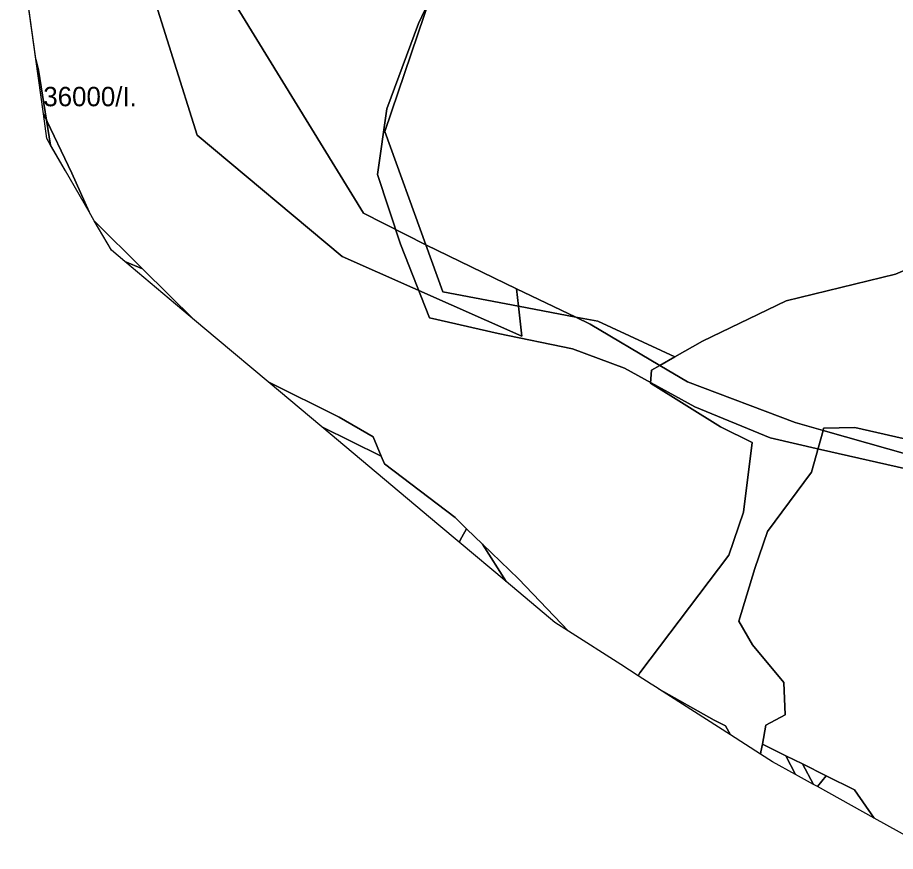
# Model space of a CAD drawing. Extents: x -537068 to -534056, y -1176840 to -1172401.
# Drawn here: x -535737.3 to -535510.5, y -1176827.8 to -1176612.4 of the extents above; entities that cross this region are included whole.
import ezdxf

# ---------------------------------------------------------------- set-up
doc = ezdxf.new("R2010")
doc.units = 0
for name, color, linetype in [('95630013', 7, 'Continuous'), ('95640013', 7, 'Continuous'), ('95660013', 7, 'Continuous')]:
    doc.layers.add(name, color=color, linetype=linetype)

msp = doc.modelspace()

# ---------------------------------------------------------------- linework, layer by layer
at = {"layer": '95630013'}
for points in [[(-535621.12, -1176508.44), (-535627.42, -1176514.05), (-535663.52, -1176546.21), (-535682.87, -1176606.01), (-535647.88, -1176662.99), (-535631.81, -1176671.18), (-535627.41, -1176683.32), (-535607.84, -1176687.01), (-535606.97, -1176694.7), (-535653.38, -1176674.17), (-535690.89, -1176642.78), (-535703.45, -1176602.79), (-535678.44, -1176529.22), (-535628.68, -1176502.86)], [(-535611.19, -1176513.92), (-535537.73, -1176516.12), (-535481.66, -1176536.93), (-535487.75, -1176593.96), (-535547.63, -1176597.67), (-535617.46, -1176602.04), (-535616.99, -1176606.16), (-535547.67, -1176601.79), (-535488.18, -1176598.05), (-535496.14, -1176672.63), (-535510.43, -1176678.69), (-535538.74, -1176685.61), (-535560.3, -1176696.02), (-535567.5, -1176700.1), (-535587.32, -1176690.88), (-535593.03, -1176689.8), (-535608.35, -1176682.47), (-535631.81, -1176671.18), (-535642.41, -1176641.9), (-535625.41, -1176591.75), (-535625.2, -1176543.89)], [(-535729.7, -1176643.72), (-535730.58, -1176637.35), (-535723.23, -1176652.66), (-535718.78, -1176662.62), (-535724.88, -1176652.06)], [(-535709.56, -1176675.47), (-535713.04, -1176672.55), (-535717.46, -1176664.91), (-535704.95, -1176677.3)], [(-535691.56, -1176690.57), (-535709.56, -1176675.47), (-535704.95, -1176677.3)], [(-535607.84, -1176687.01), (-535608.35, -1176682.47), (-535593.03, -1176689.8)], [(-535587.32, -1176690.88), (-535567.5, -1176700.1), (-535571.31, -1176702.26), (-535589.3, -1176691.59), (-535593.03, -1176689.8)], [(-535658.68, -1176718.16), (-535672.54, -1176706.53), (-535654.19, -1176715.67), (-535645.43, -1176720.75), (-535643.3, -1176725.75)], [(-535529.02, -1176718.5), (-535520.93, -1176718.34), (-535504.72, -1176722), (-535501.5, -1176722.89), (-535481.43, -1176726.23), (-535481.42, -1176725.84), (-535431.83, -1176733.13), (-535331.55, -1176707.87), (-535331.62, -1176708.58), (-535368.4, -1176721.4), (-535400.69, -1176729.98), (-535428.42, -1176735.02), (-535446.08, -1176733.53), (-535500.92, -1176727.08), (-535529.17, -1176719.06)], [(-535658.68, -1176718.16), (-535643.3, -1176725.75), (-535642.47, -1176727.68), (-535624.25, -1176741.59), (-535621.28, -1176744.45), (-535622.5, -1176746.61), (-535623.22, -1176747.9), (-535628.42, -1176743.54)], [(-535622.5, -1176746.61), (-535621.28, -1176744.45), (-535617.15, -1176748.46), (-535611.07, -1176758.1), (-535623.22, -1176747.9)], [(-535611.07, -1176758.1), (-535617.15, -1176748.46), (-535607.88, -1176757.43), (-535594.9, -1176770.95), (-535598.48, -1176768.66)], [(-535571.69, -1176785.8), (-535557.28, -1176793.89), (-535554.38, -1176795.34), (-535553.07, -1176797.71)], [(-535538.81, -1176803.08), (-535536.29, -1176807.93), (-535542.25, -1176804.63), (-535545.34, -1176802.66), (-535545.23, -1176802.1), (-535544.85, -1176800.08)], [(-535536.29, -1176807.93), (-535538.81, -1176803.08), (-535534.52, -1176805.21), (-535531.67, -1176810.49)], [(-535530.62, -1176811.07), (-535531.67, -1176810.49), (-535534.52, -1176805.21), (-535528.39, -1176808.26)], [(-535521.01, -1176811.93), (-535515.98, -1176819.18), (-535530.62, -1176811.07), (-535528.39, -1176808.26)]]:
    msp.add_lwpolyline(points, close=True, dxfattribs=at)
for points in [[(-535481.66, -1176536.93), (-535537.73, -1176516.12), (-535611.19, -1176513.92), (-535625.2, -1176543.89), (-535625.41, -1176591.75), (-535642.41, -1176641.9), (-535631.81, -1176671.18), (-535647.88, -1176662.99), (-535682.87, -1176606.01), (-535663.52, -1176546.21), (-535627.42, -1176514.05), (-535621.12, -1176508.44), (-535604.78, -1176505.41), (-535595.14, -1176505.52), (-535558.71, -1176507.19), (-535533.2, -1176510.4), (-535505.76, -1176520.73)], [(-535703.45, -1176602.79), (-535690.89, -1176642.78), (-535653.38, -1176674.17), (-535606.97, -1176694.7), (-535607.84, -1176687.01), (-535593.03, -1176689.8), (-535589.3, -1176691.59), (-535571.31, -1176702.26), (-535573.45, -1176703.47), (-535573.71, -1176706.9), (-535555.67, -1176718.13), (-535547.5, -1176722.15), (-535549.75, -1176740.16), (-535553.5, -1176751.27), (-535576.51, -1176781.66), (-535576.91, -1176782.46), (-535581.44, -1176779.56), (-535594.9, -1176770.95), (-535607.88, -1176757.43), (-535617.15, -1176748.46), (-535621.28, -1176744.45), (-535624.25, -1176741.59), (-535642.47, -1176727.68), (-535643.3, -1176725.75), (-535645.43, -1176720.75), (-535654.19, -1176715.67), (-535672.54, -1176706.53), (-535685.74, -1176695.46), (-535691.56, -1176690.57), (-535704.95, -1176677.3), (-535717.46, -1176664.91), (-535718.78, -1176662.62), (-535723.23, -1176652.66), (-535730.58, -1176637.35), (-535737.27, -1176588.86)], [(-535500.42, -1176827.8), (-535515.98, -1176819.18), (-535521.01, -1176811.93), (-535528.39, -1176808.26), (-535534.52, -1176805.21), (-535538.81, -1176803.08), (-535544.85, -1176800.08), (-535543.92, -1176795.2), (-535538.92, -1176792.48), (-535539.33, -1176784.21), (-535547.44, -1176774.42), (-535550.96, -1176768.35), (-535546.78, -1176754.69), (-535543.5, -1176745.17), (-535532.18, -1176729.85), (-535529.17, -1176719.06), (-535500.92, -1176727.08)]]:
    msp.add_lwpolyline(points, dxfattribs=at)
at = {"layer": '95640013'}
for points in [[(-535496.15, -1176700.28), (-535480.13, -1176715.73), (-535481.31, -1176720.98), (-535481.42, -1176725.84), (-535481.43, -1176726.23), (-535501.5, -1176722.89), (-535504.72, -1176722), (-535520.93, -1176718.34), (-535529.02, -1176718.5), (-535529.17, -1176719.06), (-535536.34, -1176717.02), (-535564.15, -1176706.5), (-535571.31, -1176702.26), (-535567.5, -1176700.1), (-535560.3, -1176696.02), (-535538.74, -1176685.61), (-535510.43, -1176678.69), (-535496.14, -1176672.63), (-535488.35, -1176669.33), (-535473.85, -1176669.28), (-535474.03, -1176675.92), (-535487.93, -1176678.11), (-535497.89, -1176689.03)], [(-535627.41, -1176683.32), (-535631.81, -1176671.18), (-535608.35, -1176682.47), (-535607.84, -1176687.01)], [(-535557.28, -1176793.89), (-535571.69, -1176785.8), (-535572.06, -1176785.56), (-535573.58, -1176784.59), (-535576.91, -1176782.46), (-535576.51, -1176781.66), (-535553.5, -1176751.27), (-535549.75, -1176740.16), (-535547.5, -1176722.15), (-535555.67, -1176718.13), (-535573.71, -1176706.9), (-535573.45, -1176703.47), (-535571.31, -1176702.26), (-535564.15, -1176706.5), (-535536.34, -1176717.02), (-535529.17, -1176719.06), (-535532.18, -1176729.85), (-535543.5, -1176745.17), (-535546.78, -1176754.69), (-535550.96, -1176768.35), (-535547.44, -1176774.42), (-535539.33, -1176784.21), (-535538.92, -1176792.48), (-535543.92, -1176795.2), (-535544.85, -1176800.08), (-535545.23, -1176802.1), (-535545.34, -1176802.66), (-535553.07, -1176797.71), (-535554.38, -1176795.34)]]:
    msp.add_lwpolyline(points, close=True, dxfattribs=at)
at = {"layer": '95660013'}
for points in [[(-535481.12, -1176735), (-535529.81, -1176724), (-535542.81, -1176721), (-535562.31, -1176713), (-535580.5, -1176703), (-535593.87, -1176698), (-535613.12, -1176694), (-535630.87, -1176690), (-535638.37, -1176671), (-535644.31, -1176653), (-535641.87, -1176636), (-535636.79, -1176622.32), (-535633.69, -1176614), (-535629.5, -1176605), (-535628.31, -1176583), (-535630, -1176555), (-535627, -1176544), (-535622.19, -1176534), (-535612.12, -1176524), (-535603.87, -1176522), (-535556.87, -1176524), (-535539.81, -1176526), (-535530.87, -1176529), (-535500.87, -1176540)], [(-535500.87, -1176540), (-535530.87, -1176529), (-535539.81, -1176526), (-535556.87, -1176524), (-535603.87, -1176522), (-535612.12, -1176524), (-535622.19, -1176534), (-535627, -1176544), (-535630, -1176555), (-535628.31, -1176583), (-535629.5, -1176605), (-535633.69, -1176614), (-535636.79, -1176622.32), (-535641.87, -1176636), (-535644.31, -1176653), (-535638.37, -1176671), (-535630.87, -1176690), (-535613.12, -1176694), (-535593.87, -1176698), (-535580.5, -1176703), (-535562.31, -1176713), (-535542.81, -1176721), (-535529.81, -1176724), (-535481.12, -1176735)], [(-535500.42, -1176827.8), (-535515.98, -1176819.18), (-535530.62, -1176811.07), (-535531.67, -1176810.49), (-535536.29, -1176807.93), (-535542.25, -1176804.63), (-535545.34, -1176802.66), (-535553.07, -1176797.71), (-535571.69, -1176785.8), (-535572.06, -1176785.56), (-535573.58, -1176784.59), (-535576.91, -1176782.46), (-535581.44, -1176779.56), (-535594.9, -1176770.95), (-535598.48, -1176768.66), (-535611.07, -1176758.1), (-535623.22, -1176747.9), (-535628.42, -1176743.54), (-535658.68, -1176718.16), (-535672.54, -1176706.53), (-535685.74, -1176695.46), (-535691.56, -1176690.57), (-535709.56, -1176675.47), (-535713.04, -1176672.55), (-535717.46, -1176664.91), (-535718.78, -1176662.62), (-535724.88, -1176652.06), (-535728.72, -1176645.41), (-535731.87, -1176626), (-535732.53, -1176623.21), (-535734.67, -1176607.7)]]:
    msp.add_lwpolyline(points, dxfattribs=at)
msp.add_lwpolyline([(-535729.7, -1176643.72), (-535730.58, -1176637.35), (-535732.53, -1176623.21), (-535731.87, -1176626), (-535728.72, -1176645.41)], close=True, dxfattribs=at)

# ---------------------------------------------------------------- texts
msp.add_text('36000/I.', height=5, rotation=360, dxfattribs=at).set_placement((-535730.62, -1176635.35))

doc.saveas('drawing.dxf')
